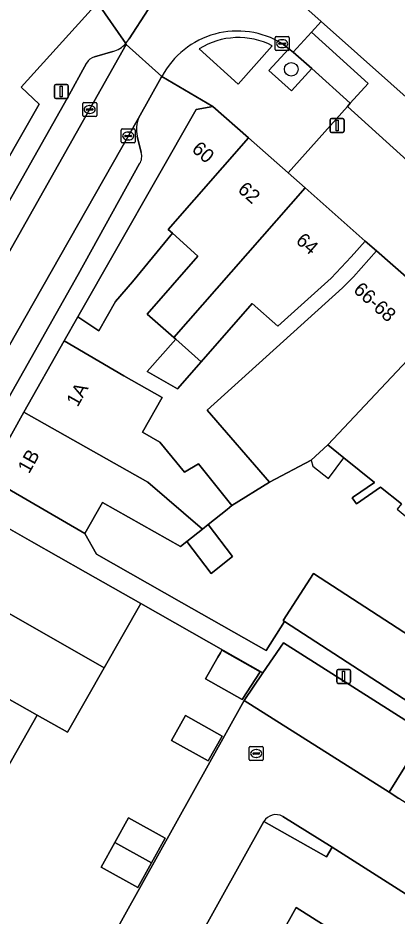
# Model space of a CAD drawing. Extents: x 161798 to 162385, y 382315 to 382833.
# Drawn here: x 162038.1 to 162065.3, y 382659.8 to 382724.1 of the extents above; entities that cross this region are included whole.
import ezdxf

# ---------------------------------------------------------------- set-up
doc = ezdxf.new("R2010")
doc.units = 0
for name, color, linetype in [('IMGEO_Boom', 7, 'Continuous'), ('IMGEO_Erf', 7, 'Continuous'), ('IMGEO_Groenvoorziening', 7, 'Continuous'), ('IMGEO_Kolk', 7, 'Continuous'), ('IMGEO_Lichtmast', 7, 'Continuous'), ('IMGEO_Pand', 7, 'Continuous'), ('IMGEO_Pand_nummerreeks', 7, 'Continuous'), ('IMGEO_Pand_overbouw', 7, 'Continuous'), ('IMGEO_Parkeervlak_open', 7, 'Continuous'), ('IMGEO_Rijbaan_lokaal_gesloten', 7, 'Continuous'), ('IMGEO_Rijbaan_lokaal_open', 7, 'Continuous'), ('IMGEO_Voetpad_open', 7, 'Continuous')]:
    doc.layers.add(name, color=color, linetype=linetype)

msp = doc.modelspace()

# ---------------------------------------------------------------- linework, layer by layer
at = {"layer": 'IMGEO_Boom'}
msp.add_circle((162057.671, 382720.382), 0.489, dxfattribs=at)
at = {"layer": 'IMGEO_Erf'}
for points in [[(162054.885, 382703.609), (162051.229, 382699.45), (162049.531, 382697.518), (162047.361, 382698.741), (162049.398, 382701.059), (162049.255, 382701.185), (162047.345, 382702.864), (162050.993, 382707.014), (162049.167, 382708.647), (162046.303, 382705.159), (162045.077, 382703.764), (162043.886, 382701.658), (162042.388, 382702.667), (162041.406, 382700.942), (162045.675, 382698.44), (162048.427, 382696.889), (162047.027, 382694.405), (162048.274, 382693.702), (162050.031, 382691.551), (162051.025, 382692.139), (162053.427, 382689.158), (162056.115, 382690.838), (162051.665, 382695.984), (162061.335, 382704.746), (162062.132, 382705.518), (162063.786, 382707.393), (162062.975, 382708.088), (162061.975, 382706.957), (162060.542, 382705.434), (162056.718, 382701.997)], [(162052.423, 382678.3), (162052.604, 382678.618), (162052.709, 382678.802), (162055.451, 382677.255), (162054.15, 382675.275), (162051.54, 382676.748)], [(162049.103, 382672.349), (162050.099, 382674.132), (162052.721, 382672.652), (162051.723, 382670.891)], [(162044.055, 382663.279), (162045.037, 382665.045), (162046.019, 382666.81), (162048.646, 382665.348), (162047.663, 382663.589), (162046.681, 382661.83)]]:
    msp.add_lwpolyline(points, close=True, dxfattribs=at)
for points in [[(162065.565, 382689.273), (162064.067, 382690.471), (162062.344, 382689.282), (162062.042, 382689.714), (162062.132, 382689.777), (162063.637, 382690.816), (162061.439, 382692.575), (162060.288, 382693.496), (162059.11, 382692.406), (162056.115, 382690.838), (162053.427, 382689.158), (162053.075, 382688.879), (162051.723, 382687.804), (162053.466, 382685.511), (162051.929, 382684.291), (162050.186, 382686.583), (162049.749, 382686.236), (162044.156, 382689.388), (162042.902, 382687.163), (162043.726, 382685.685), (162049.81, 382682.222), (162051.971, 382680.991), (162055.869, 382678.772), (162057.2, 382680.869), (162057.1, 382680.934), (162059.268, 382684.293), (162074.525, 382674.387)], [(162037.089, 382644.31), (162054.299, 382675.209), (162055.644, 382677.181), (162051.771, 382679.386), (162046.908, 382682.155), (162044.28, 382677.542), (162041.652, 382672.93), (162039.481, 382674.159), (162036.925, 382669.634), (162034.369, 382665.109), (162036.559, 382663.871), (162033.985, 382659.354), (162031.821, 382660.586), (162029.259, 382656.056)]]:
    msp.add_lwpolyline(points, dxfattribs=at)
at = {"layer": 'IMGEO_Groenvoorziening'}
msp.add_lwpolyline([(162051.088, 382721.849), (162053.872, 382719.313), (162056.315, 382722.073)], dxfattribs=at)
msp.add_lwpolyline([(162057.817, 382721.616), (162057.495, 382721.854), (162056.073, 382720.29), (162057.698, 382718.831), (162059.143, 382720.435)], close=True, dxfattribs=at)
msp.add_arc((162053.9, 382717.335), 5.318, 62.99137, 121.91638, dxfattribs=at)
at = {"layer": 'IMGEO_Kolk'}
for p, q in [((162056.523, 382721.793), (162056.523, 382722.645)), ((162056.598, 382722.719), (162057.45, 382722.719)), ((162057.011, 382722.499), (162057.036, 382722.499)), ((162057.524, 382722.645), (162057.524, 382721.793)), ((162056.782, 382722.213), (162056.782, 382722.225)), ((162057.22, 382722.176), (162056.822, 382722.176)), ((162056.825, 382722.262), (162057.223, 382722.262)), ((162057.034, 382721.939), (162057.009, 382721.939)), ((162057.266, 382722.225), (162057.266, 382722.213)), ((162057.45, 382721.719), (162056.598, 382721.719)), ((162042.814, 382718.005), (162043.666, 382718.005)), ((162042.739, 382717.079), (162042.739, 382717.931)), ((162042.998, 382717.499), (162042.998, 382717.511)), ((162043.436, 382717.462), (162043.038, 382717.462)), ((162043.041, 382717.548), (162043.439, 382717.548)), ((162043.227, 382717.785), (162043.252, 382717.785)), ((162043.482, 382717.511), (162043.482, 382717.499)), ((162043.74, 382717.931), (162043.74, 382717.079)), ((162043.666, 382717.005), (162042.814, 382717.005)), ((162043.25, 382717.225), (162043.225, 382717.225)), ((162045.576, 382716.111), (162046.428, 382716.111)), ((162045.501, 382715.185), (162045.501, 382716.037)), ((162045.76, 382715.605), (162045.76, 382715.617)), ((162046.198, 382715.568), (162045.8, 382715.568)), ((162045.803, 382715.654), (162046.201, 382715.654)), ((162045.989, 382715.891), (162046.014, 382715.891)), ((162046.244, 382715.617), (162046.244, 382715.605)), ((162046.502, 382716.037), (162046.502, 382715.185)), ((162046.428, 382715.111), (162045.576, 382715.111)), ((162046.012, 382715.331), (162045.987, 382715.331)), ((162054.667, 382670.987), (162054.667, 382671.839)), ((162054.742, 382671.913), (162055.594, 382671.913)), ((162055.668, 382671.839), (162055.668, 382670.987)), ((162054.926, 382671.407), (162054.926, 382671.419)), ((162055.364, 382671.37), (162054.966, 382671.37)), ((162054.969, 382671.456), (162055.367, 382671.456)), ((162055.178, 382671.133), (162055.153, 382671.133)), ((162055.155, 382671.693), (162055.18, 382671.693)), ((162055.41, 382671.419), (162055.41, 382671.407)), ((162055.594, 382670.913), (162054.742, 382670.913))]:
    msp.add_line(p, q, dxfattribs=at)
for points in [[(162056.523, 382721.793), (162056.523, 382722.645)], [(162056.598, 382722.719), (162057.45, 382722.719)], [(162057.524, 382722.645), (162057.524, 382721.793)], [(162057.45, 382721.719), (162056.598, 382721.719)], [(162042.814, 382718.005), (162043.666, 382718.005)], [(162042.739, 382717.079), (162042.739, 382717.931)], [(162043.74, 382717.931), (162043.74, 382717.079)], [(162043.666, 382717.005), (162042.814, 382717.005)], [(162045.576, 382716.111), (162046.428, 382716.111)], [(162045.501, 382715.185), (162045.501, 382716.037)], [(162046.502, 382716.037), (162046.502, 382715.185)], [(162046.428, 382715.111), (162045.576, 382715.111)], [(162054.667, 382670.987), (162054.667, 382671.839)], [(162054.742, 382671.913), (162055.594, 382671.913)], [(162055.668, 382671.839), (162055.668, 382670.987)], [(162055.594, 382670.913), (162054.742, 382670.913)]]:
    msp.add_lwpolyline(points, dxfattribs=at)
for centre, radius, start, end in [((162056.6, 382722.643), 0.0765, 91.55205, 178.44795), ((162056.6, 382722.643), 0.0765, 91.55205, 178.44795), ((162057.448, 382722.643), 0.0765, 1.55205, 88.44795), ((162057.448, 382722.643), 0.0765, 1.55205, 88.44795), ((162056.822, 382722.222), 0.0403, 85.87752, 175.75265), ((162056.819, 382722.212), 0.0366, 178.93798, 274.71019), ((162057.223, 382722.219), 0.043, 264.86636, 352.45326), ((162057.227, 382722.224), 0.0386, 1.73085, 96.63898), ((162056.6, 382721.795), 0.0765, 181.55205, 268.44795), ((162056.6, 382721.795), 0.0765, 181.55205, 268.44795), ((162057.448, 382721.795), 0.0765, 271.55205, 358.44795), ((162057.448, 382721.795), 0.0765, 271.55205, 358.44795), ((162042.816, 382717.929), 0.0765, 91.55205, 178.44795), ((162042.816, 382717.929), 0.0765, 91.55205, 178.44795), ((162043.664, 382717.929), 0.0765, 1.55205, 88.44795), ((162043.664, 382717.929), 0.0765, 1.55205, 88.44795), ((162043.038, 382717.508), 0.0403, 85.87752, 175.75265), ((162043.035, 382717.498), 0.0366, 178.93798, 274.71019), ((162043.439, 382717.505), 0.043, 264.86636, 352.45326), ((162043.443, 382717.51), 0.0386, 1.73085, 96.63898), ((162042.816, 382717.081), 0.0765, 181.55205, 268.44795), ((162042.816, 382717.081), 0.0765, 181.55205, 268.44795), ((162043.664, 382717.081), 0.0765, 271.55205, 358.44795), ((162043.664, 382717.081), 0.0765, 271.55205, 358.44795), ((162045.578, 382716.035), 0.0765, 91.55205, 178.44795), ((162045.578, 382716.035), 0.0765, 91.55205, 178.44795), ((162046.426, 382716.035), 0.0765, 1.55205, 88.44795), ((162046.426, 382716.035), 0.0765, 1.55205, 88.44795), ((162045.8, 382715.614), 0.0403, 85.87752, 175.75265), ((162045.797, 382715.604), 0.0366, 178.93798, 274.71019), ((162046.201, 382715.611), 0.043, 264.86636, 352.45326), ((162046.205, 382715.616), 0.0386, 1.73085, 96.63898), ((162045.578, 382715.187), 0.0765, 181.55205, 268.44795), ((162045.578, 382715.187), 0.0765, 181.55205, 268.44795), ((162046.426, 382715.187), 0.0765, 271.55205, 358.44795), ((162046.426, 382715.187), 0.0765, 271.55205, 358.44795), ((162054.744, 382671.837), 0.0765, 91.55205, 178.44795), ((162054.744, 382671.837), 0.0765, 91.55205, 178.44795), ((162055.592, 382671.837), 0.0765, 1.55205, 88.44795), ((162055.592, 382671.837), 0.0765, 1.55205, 88.44795), ((162054.966, 382671.416), 0.0403, 85.87752, 175.75265), ((162054.963, 382671.406), 0.0366, 178.93798, 274.71019), ((162055.367, 382671.413), 0.043, 264.86636, 352.45326), ((162055.371, 382671.418), 0.0386, 1.73085, 96.63898), ((162054.744, 382670.989), 0.0765, 181.55205, 268.44795), ((162054.744, 382670.989), 0.0765, 181.55205, 268.44795), ((162055.592, 382670.989), 0.0765, 271.55205, 358.44795), ((162055.592, 382670.989), 0.0765, 271.55205, 358.44795)]:
    msp.add_arc(centre, radius, start, end, dxfattribs=at)
for centre, major_axis, ratio, start_param, end_param in [((162057.01, 382722.219), (-0.387, 0.002), 0.722429, 4.712389, 7.853982), ((162057.035, 382722.219), (-0.39, 0.002), 0.717154, 1.570796, 4.712389), ((162043.226, 382717.505), (-0.387, 0.002), 0.722429, 4.712389, 7.853982), ((162043.251, 382717.505), (-0.39, 0.002), 0.717154, 1.570796, 4.712389), ((162045.988, 382715.611), (-0.387, 0.002), 0.722429, 4.712389, 7.853982), ((162046.013, 382715.611), (-0.39, 0.002), 0.717154, 1.570796, 4.712389), ((162055.154, 382671.413), (-0.387, 0.002), 0.722429, 4.712389, 7.853982), ((162055.179, 382671.413), (-0.39, 0.002), 0.717154, 1.570796, 4.712389)]:
    msp.add_ellipse(centre, major_axis=major_axis, ratio=ratio, start_param=start_param, end_param=end_param, dxfattribs=at)
at = {"layer": 'IMGEO_Lichtmast'}
for p, q in [((162040.809, 382719.297), (162041.599, 382719.297)), ((162041.599, 382719.297), (162040.809, 382719.297)), ((162040.709, 382718.397), (162040.709, 382719.197)), ((162040.709, 382719.197), (162040.709, 382718.397)), ((162041.699, 382719.197), (162041.699, 382718.397)), ((162041.699, 382718.397), (162041.699, 382719.197)), ((162041.599, 382718.297), (162040.809, 382718.297)), ((162040.809, 382718.297), (162041.599, 382718.297)), ((162060.468, 382715.961), (162060.468, 382716.761)), ((162060.468, 382716.761), (162060.468, 382715.961)), ((162060.568, 382716.861), (162061.358, 382716.861)), ((162061.358, 382716.861), (162060.568, 382716.861)), ((162061.458, 382716.761), (162061.458, 382715.961)), ((162061.458, 382715.961), (162061.458, 382716.761)), ((162061.358, 382715.861), (162060.568, 382715.861)), ((162060.568, 382715.861), (162061.358, 382715.861)), ((162060.931, 382676.529), (162060.931, 382677.329)), ((162060.931, 382677.329), (162060.931, 382676.529)), ((162061.031, 382677.429), (162061.821, 382677.429)), ((162061.821, 382677.429), (162061.031, 382677.429)), ((162061.921, 382677.329), (162061.921, 382676.529)), ((162061.921, 382676.529), (162061.921, 382677.329)), ((162061.821, 382676.429), (162061.031, 382676.429)), ((162061.031, 382676.429), (162061.821, 382676.429))]:
    msp.add_line(p, q, dxfattribs=at)
for points in [[(162041.129, 382719.172), (162041.279, 382719.172), (162041.279, 382718.422), (162041.129, 382718.422), (162041.129, 382719.172)], [(162060.888, 382716.736), (162061.038, 382716.736), (162061.038, 382715.986), (162060.888, 382715.986), (162060.888, 382716.736)], [(162061.351, 382677.304), (162061.501, 382677.304), (162061.501, 382676.554), (162061.351, 382676.554), (162061.351, 382677.304)]]:
    msp.add_lwpolyline(points, dxfattribs=at)
for centre, start, end in [((162040.809, 382719.197), 90, 180), ((162040.809, 382719.197), 90, 180), ((162041.599, 382719.197), 0, 90), ((162041.599, 382719.197), 360, 90), ((162040.809, 382718.397), 180, 270), ((162040.809, 382718.397), 180, 270), ((162041.599, 382718.397), 270, 0), ((162041.599, 382718.397), 270, 0), ((162060.568, 382716.761), 90, 180), ((162060.568, 382716.761), 90, 180), ((162061.358, 382716.761), 0, 90), ((162061.358, 382716.761), 360, 90), ((162060.568, 382715.961), 180, 270), ((162060.568, 382715.961), 180, 270), ((162061.358, 382715.961), 270, 0), ((162061.358, 382715.961), 270, 0), ((162061.031, 382677.329), 90, 180), ((162061.031, 382677.329), 90, 180), ((162061.821, 382677.329), 0, 90), ((162061.821, 382677.329), 360, 90), ((162061.031, 382676.529), 180, 270), ((162061.031, 382676.529), 180, 270), ((162061.821, 382676.529), 270, 0), ((162061.821, 382676.529), 270, 0)]:
    msp.add_arc(centre, 0.1, start, end, dxfattribs=at)
at = {"layer": 'IMGEO_Pand'}
for points in [[(162043.809, 382725.145), (162038.012, 382730.344), (162031.391, 382722.985), (162034.809, 382719.922), (162031.855, 382714.755), (162030.255, 382715.747), (162027.277, 382718.416), (162020.899, 382711.331), (162021.086, 382711.145), (162027.742, 382707.225), (162032.096, 382704.768), (162039.623, 382717.887), (162038.323, 382719.109)], [(162046.303, 382705.159), (162049.167, 382708.647), (162048.862, 382708.915), (162054.623, 382715.469), (162052.067, 382717.728), (162050.871, 382717.515), (162042.388, 382702.667), (162043.886, 382701.658), (162045.077, 382703.764)], [(162058.669, 382711.893), (162057.449, 382712.971), (162054.623, 382715.469), (162048.862, 382708.915), (162049.167, 382708.647), (162050.993, 382707.014), (162047.345, 382702.864), (162049.255, 382701.185)], [(162060.542, 382705.434), (162061.975, 382706.957), (162062.975, 382708.088), (162058.669, 382711.893), (162049.255, 382701.185), (162049.398, 382701.059), (162051.229, 382699.45), (162054.885, 382703.609), (162056.718, 382701.997)], [(162060.288, 382693.496), (162069.024, 382702.773), (162063.786, 382707.393), (162062.132, 382705.518), (162061.335, 382704.746), (162051.665, 382695.984), (162056.115, 382690.838), (162059.11, 382692.406)], [(162083.043, 382691.165), (162078.004, 382695.105), (162075.398, 382697.265), (162074.414, 382698.042), (162069.243, 382702.571), (162069.144, 382702.458), (162069.007, 382702.578), (162069.111, 382702.696), (162069.024, 382702.773), (162060.288, 382693.496), (162061.439, 382692.575), (162063.637, 382690.816), (162062.132, 382689.777), (162062.042, 382689.714), (162062.344, 382689.282), (162064.067, 382690.471), (162065.565, 382689.273), (162065.263, 382688.889), (162066.395, 382687.976), (162066.717, 382688.359), (162078.981, 382678.576), (162080.055, 382677.948), (162087.494, 382688.013)], [(162047.027, 382694.405), (162048.427, 382696.889), (162045.675, 382698.44), (162041.406, 382700.942), (162038.529, 382695.832), (162047.401, 382690.835), (162051.31, 382687.476), (162051.723, 382687.804), (162053.075, 382688.879), (162053.427, 382689.158), (162051.025, 382692.139), (162050.031, 382691.551), (162048.274, 382693.702)], [(162051.229, 382699.45), (162049.398, 382701.059), (162047.361, 382698.741), (162049.531, 382697.518)], [(162047.401, 382690.835), (162038.529, 382695.832), (162035.919, 382691.194), (162036.014, 382691.139), (162042.902, 382687.163), (162044.156, 382689.388), (162049.749, 382686.236), (162050.186, 382686.583), (162051.31, 382687.476)], [(162035.537, 382688.587), (162032.949, 382683.998), (162044.28, 382677.542), (162046.908, 382682.155), (162042.945, 382684.396), (162039.07, 382686.589)], [(162051.723, 382687.804), (162051.31, 382687.476), (162050.186, 382686.583), (162051.929, 382684.291), (162053.466, 382685.511)], [(162032.949, 382683.998), (162030.318, 382679.335), (162039.481, 382674.159), (162041.652, 382672.93), (162044.28, 382677.542)], [(162059.268, 382684.293), (162057.1, 382680.934), (162057.2, 382680.869), (162072.358, 382671.028), (162074.525, 382674.387)], [(162039.481, 382674.159), (162030.318, 382679.335), (162027.764, 382674.809), (162036.925, 382669.634)], [(162052.423, 382678.3), (162051.54, 382676.748), (162054.15, 382675.275), (162055.451, 382677.255), (162052.709, 382678.802), (162052.604, 382678.618)], [(162049.103, 382672.349), (162051.723, 382670.891), (162052.721, 382672.652), (162050.099, 382674.132)], [(162045.037, 382665.045), (162047.663, 382663.589), (162048.646, 382665.348), (162046.019, 382666.81)], [(162047.663, 382663.589), (162045.037, 382665.045), (162044.055, 382663.279), (162046.681, 382661.83)]]:
    msp.add_lwpolyline(points, close=True, dxfattribs=at)
at = {"layer": 'IMGEO_Pand_overbouw'}
msp.add_lwpolyline([(162060.335, 382691.085), (162061.439, 382692.575), (162060.288, 382693.496), (162059.11, 382692.406), (162059.227, 382691.972)], close=True, dxfattribs=at)
at = {"layer": 'IMGEO_Parkeervlak_open'}
for points in [[(162031.601, 382696.918), (162032.04, 382697.695), (162045.858, 382722.165)], [(162045.858, 382722.165), (162045.819, 382722.219)], [(162044.908, 382721.664), (162043.576, 382721.271)], [(162043.019, 382720.833), (162041.66, 382718.336), (162037.138, 382710.354), (162035.478, 382707.418), (162031.379, 382700.168)], [(162046.73, 382716.896), (162034.906, 382696.099), (162034.536, 382695.447)], [(162046.925, 382714.424), (162046.648, 382715.608)], [(162037.462, 382696.935), (162042.426, 382705.699), (162046.814, 382713.629)]]:
    msp.add_lwpolyline(points, dxfattribs=at)
for points in [[(162057.115, 382679.339), (162055.644, 382677.181), (162054.299, 382675.209), (162064.691, 382668.651), (162067.312, 382672.878)], [(162085.335, 382645.581), (162086.876, 382648.006), (162060.601, 382664.717), (162060.21, 382664.005), (162055.713, 382666.546), (162045.947, 382649.007), (162050.322, 382646.559), (162058.029, 382660.392), (162084.208, 382643.821)]]:
    msp.add_lwpolyline(points, close=True, dxfattribs=at)
for centre, radius, start, end in [((162044.468, 382723.411), 1.801, 284.12763, 318.57364), ((162043.916, 382720.265), 1.062, 108.68383, 147.67604), ((162048.731, 382716.122), 2.145, 158.8527, 193.86171), ((162046.06, 382714.14), 0.911, 325.90621, 18.19698)]:
    msp.add_arc(centre, radius, start, end, dxfattribs=at)
at = {"layer": 'IMGEO_Rijbaan_lokaal_gesloten'}
msp.add_lwpolyline([(162059.12, 382723.035), (162057.817, 382721.616), (162059.143, 382720.435), (162061.886, 382717.951), (162063.175, 382719.373)], close=True, dxfattribs=at)
at = {"layer": 'IMGEO_Rijbaan_lokaal_open'}
for points in [[(162059.829, 382723.81), (162050.126, 382732.448), (162049.418, 382731.719), (162048.13, 382730.285)], [(162048.78, 382726.777), (162046.062, 382722.574)], [(162057.024, 382722.219), (162057.495, 382721.854), (162057.817, 382721.616), (162059.12, 382723.035), (162059.829, 382723.81)], [(162140.733, 382663.262), (162095.172, 382692.349), (162059.829, 382723.81), (162059.12, 382723.035), (162063.175, 382719.373), (162061.886, 382717.951), (162061.695, 382717.709), (162069.75, 382710.451), (162071.409, 382708.931), (162075.668, 382705.123)], [(162045.819, 382722.219), (162045.858, 382722.165), (162048.416, 382719.879)], [(162094.025, 382644.065), (162096.732, 382648.306), (162088.266, 382653.675), (162087.562, 382654.137), (162076.445, 382661.19), (162075.75, 382661.625), (162065.37, 382668.189), (162064.691, 382668.651), (162054.299, 382675.209), (162037.089, 382644.31), (162037.04, 382644.222)], [(162057.065, 382666.906), (162060.601, 382664.717), (162086.876, 382648.006), (162085.335, 382645.581), (162085.636, 382644.628)], [(162043.256, 382644.219), (162043.816, 382645.215), (162043.915, 382645.073), (162045.358, 382647.784), (162045.283, 382647.826), (162045.429, 382648.086), (162045.947, 382649.007), (162055.713, 382666.546)]]:
    msp.add_lwpolyline(points, dxfattribs=at)
msp.add_lwpolyline([(162046.73, 382716.896), (162048.367, 382719.786), (162048.416, 382719.879), (162045.858, 382722.165), (162032.04, 382697.695), (162034.906, 382696.099)], close=True, dxfattribs=at)
for centre, radius, start, end in [((162053.821, 382716.998), 6.125, 58.47401, 151.94159), ((162044.466, 382723.406), 1.8, 318.74355, 332.47262), ((162056.571, 382666.043), 0.994, 60.20206, 149.61857)]:
    msp.add_arc(centre, radius, start, end, dxfattribs=at)
at = {"layer": 'IMGEO_Voetpad_open'}
for points in [[(161994.37, 382772.717), (161991.783, 382769.02), (161991.848, 382768.97), (161997.519, 382764.558), (161998.609, 382765.767), (162000, 382764.491), (162003.821, 382761.079), (162009.776, 382755.729), (162015.335, 382750.798), (162016.083, 382750.117), (162017.324, 382748.986), (162022.858, 382743.945), (162027.754, 382739.543), (162038.012, 382730.344), (162043.809, 382725.145), (162045.819, 382722.219)], [(162046.062, 382722.574), (162048.78, 382726.777)], [(162045.819, 382722.219), (162043.809, 382725.145), (162038.323, 382719.109), (162039.623, 382717.887), (162032.096, 382704.768), (162030.046, 382701.359), (162026.271, 382694.655), (162022.485, 382687.932), (162019.684, 382682.959), (162015.615, 382675.734), (162015.046, 382674.723), (162012.489, 382670.184), (162009.351, 382664.611), (162005.425, 382657.64), (162002.666, 382652.742), (162000, 382648.009), (161998.381, 382645.135), (161995.375, 382646.828), (161994.867, 382646.022), (161990.55, 382641.902), (161994.605, 382633.896), (161994.989, 382632.3)], [(162056.315, 382722.073), (162053.872, 382719.313), (162051.088, 382721.849)], [(162056.073, 382720.29), (162057.495, 382721.854), (162057.024, 382722.219)], [(162043.576, 382721.271), (162044.908, 382721.664)], [(162031.379, 382700.168), (162030.945, 382700.414), (162035.052, 382707.66), (162035.478, 382707.418), (162037.138, 382710.354), (162041.66, 382718.336), (162043.019, 382720.833)], [(162048.416, 382719.879), (162052.067, 382717.728), (162054.623, 382715.469), (162057.449, 382712.971), (162061.695, 382717.709), (162061.886, 382717.951), (162059.143, 382720.435), (162057.698, 382718.831), (162056.073, 382720.29)], [(162038.529, 382695.832), (162041.406, 382700.942), (162042.388, 382702.667), (162050.871, 382717.515), (162052.067, 382717.728), (162048.416, 382719.879), (162048.367, 382719.786), (162046.73, 382716.896)], [(162069.75, 382710.451), (162061.695, 382717.709), (162057.449, 382712.971), (162058.669, 382711.893), (162062.975, 382708.088), (162063.786, 382707.393), (162069.024, 382702.773)], [(162046.648, 382715.608), (162046.925, 382714.424)], [(162046.814, 382713.629), (162042.426, 382705.699), (162037.462, 382696.935)], [(162005.834, 382642.583), (162010.84, 382642.761), (162010.786, 382644.712), (162012.434, 382647.634), (162014.858, 382651.931), (162017.55, 382656.702), (162020.106, 382661.234), (162022.663, 382665.766), (162025.211, 382670.282), (162027.764, 382674.809), (162030.318, 382679.335), (162032.949, 382683.998), (162035.537, 382688.587), (162034.816, 382688.989), (162036.014, 382691.139), (162035.919, 382691.194), (162038.529, 382695.832)], [(162072.358, 382671.028), (162057.2, 382680.869), (162055.869, 382678.772), (162051.971, 382680.991), (162049.81, 382682.222), (162043.726, 382685.685), (162042.902, 382687.163), (162036.014, 382691.139), (162034.816, 382688.989), (162035.537, 382688.587), (162039.07, 382686.589), (162042.945, 382684.396), (162046.908, 382682.155), (162051.771, 382679.386), (162055.644, 382677.181), (162057.115, 382679.339), (162067.312, 382672.878), (162064.691, 382668.651), (162065.37, 382668.189)], [(162055.713, 382666.546), (162060.21, 382664.005), (162060.601, 382664.717), (162057.065, 382666.906)]]:
    msp.add_lwpolyline(points, dxfattribs=at)
msp.add_lwpolyline([(162058.029, 382660.392), (162050.322, 382646.559), (162045.947, 382649.007), (162045.429, 382648.086), (162046.464, 382647.504), (162049.772, 382645.572), (162050.703, 382645.029), (162058.5, 382658.78), (162084.298, 382642.637), (162085.636, 382644.628), (162085.335, 382645.581), (162084.208, 382643.821)], close=True, dxfattribs=at)
for centre, radius, start, end in [((162053.821, 382716.998), 6.125, 58.47401, 151.94159), ((162044.466, 382723.406), 1.8, 318.74355, 332.47262), ((162053.9, 382717.335), 5.318, 62.99137, 121.91638), ((162044.468, 382723.411), 1.801, 284.12763, 318.57364), ((162043.916, 382720.265), 1.062, 108.68383, 147.67604), ((162048.731, 382716.122), 2.145, 158.8527, 193.86171), ((162046.06, 382714.14), 0.911, 325.90621, 18.19698), ((162056.571, 382666.043), 0.994, 60.20206, 149.61857)]:
    msp.add_arc(centre, radius, start, end, dxfattribs=at)

# ---------------------------------------------------------------- texts
at = {"layer": 'IMGEO_Pand_nummerreeks'}
for s, rotation, p in [('60', 318.6883, (162050.485, 382714.571)), ('62', 318.67828, (162053.779, 382711.676)), ('64', 318.67255, (162057.939, 382708.019)), ('66-68', 318.27049, (162062.061, 382704.499)), ('1A', 60.59602, (162042.375, 382696.163)), ('1B', 60.63039, (162038.894, 382691.384))]:
    msp.add_text(s, height=1, rotation=rotation, dxfattribs=at).set_placement(p)

doc.saveas('drawing.dxf')
